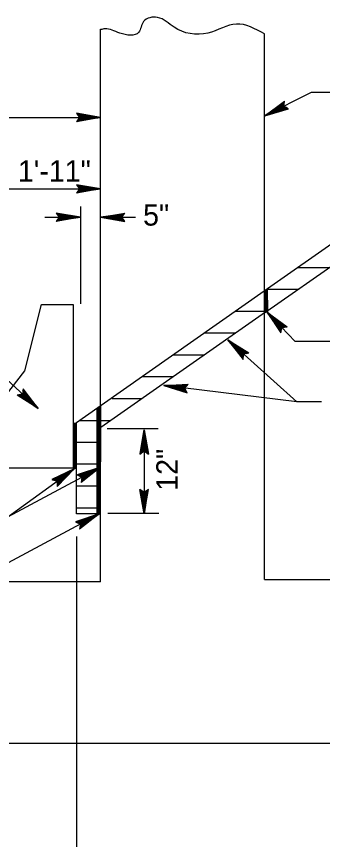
# Model space of a CAD drawing. Extents: x 1553195 to 1553792, y 810516 to 810787.
# Drawn here: x 1553765.27 to 1553772.77, y 810723.14 to 810743.32 of the extents above; entities that cross this region are included whole.
import ezdxf

# ---------------------------------------------------------------- set-up
doc = ezdxf.new("R2010")
doc.units = 0
doc.layers.add('Old_Level_28', color=7, linetype='Continuous')

msp = doc.modelspace()

# ---------------------------------------------------------------- linework, layer by layer
at = {"layer": 'Old_Level_28'}
for p, q in [((1553767.332, 810729.461), (1553767.332, 810743.008)), ((1553771.348, 810729.513), (1553771.348, 810742.899)), ((1553772.494, 810741.457), (1553771.357, 810740.888)), ((1553773.479, 810741.457), (1553772.494, 810741.457)), ((1553771.357, 810740.888), (1553771.843, 810741.248)), ((1553771.357, 810740.888), (1553771.839, 810741.23)), ((1553771.837, 810741.21), (1553771.357, 810740.888)), ((1553771.357, 810740.888), (1553771.835, 810741.193)), ((1553771.83, 810741.175), (1553771.357, 810740.888)), ((1553771.357, 810740.888), (1553771.826, 810741.155)), ((1553771.823, 810741.137), (1553771.357, 810740.888)), ((1553771.822, 810741.122), (1553771.357, 810740.888)), ((1553771.822, 810741.122), (1553771.843, 810741.248)), ((1553771.937, 810741.061), (1553771.822, 810741.122)), ((1553767.332, 810740.846), (1553766.739, 810740.948)), ((1553766.739, 810740.948), (1553766.815, 810740.846)), ((1553766.748, 810740.933), (1553767.332, 810740.846)), ((1553767.332, 810740.846), (1553766.759, 810740.92)), ((1553771.357, 810740.888), (1553771.837, 810741.11)), ((1553771.855, 810741.102), (1553771.357, 810740.888)), ((1553771.357, 810740.888), (1553771.871, 810741.095)), ((1553771.888, 810741.086), (1553771.357, 810740.888)), ((1553771.357, 810740.888), (1553771.904, 810741.077)), ((1553771.921, 810741.07), (1553771.357, 810740.888)), ((1553771.357, 810740.888), (1553771.937, 810741.061)), ((1553752.957, 810740.846), (1553767.332, 810740.846)), ((1553767.332, 810740.846), (1553766.739, 810740.739)), ((1553766.815, 810740.846), (1553766.739, 810740.739)), ((1553767.332, 810740.846), (1553766.748, 810740.754)), ((1553766.759, 810740.768), (1553767.332, 810740.846)), ((1553766.773, 810740.904), (1553767.332, 810740.846)), ((1553767.332, 810740.846), (1553766.773, 810740.784)), ((1553767.332, 810740.846), (1553766.781, 810740.888)), ((1553766.781, 810740.799), (1553767.332, 810740.846)), ((1553766.794, 810740.875), (1553767.332, 810740.846)), ((1553767.332, 810740.846), (1553766.794, 810740.813)), ((1553767.332, 810740.846), (1553766.806, 810740.859)), ((1553766.806, 810740.828), (1553767.332, 810740.846)), ((1553766.815, 810740.846), (1553767.332, 810740.846)), ((1553771.344, 810736.595), (1553776.608, 810740.281)), ((1553771.324, 810736.035), (1553776.864, 810739.914)), ((1553767.332, 810739.095), (1553766.739, 810739.197)), ((1553766.739, 810739.197), (1553766.815, 810739.095)), ((1553766.748, 810739.181), (1553767.332, 810739.095)), ((1553767.332, 810739.095), (1553766.759, 810739.168)), ((1553766.773, 810739.152), (1553767.332, 810739.095)), ((1553767.332, 810739.095), (1553766.781, 810739.137)), ((1553766.794, 810739.123), (1553767.332, 810739.095)), ((1553767.332, 810739.095), (1553766.806, 810739.108)), ((1553764.653, 810739.095), (1553767.332, 810739.095)), ((1553767.332, 810739.095), (1553766.739, 810738.988)), ((1553766.815, 810739.095), (1553766.739, 810738.988)), ((1553767.332, 810739.095), (1553766.748, 810739.004)), ((1553766.759, 810739.017), (1553767.332, 810739.095)), ((1553767.332, 810739.095), (1553766.773, 810739.032)), ((1553766.781, 810739.048), (1553767.332, 810739.095)), ((1553767.332, 810739.095), (1553766.794, 810739.061)), ((1553766.806, 810739.077), (1553767.332, 810739.095)), ((1553766.815, 810739.095), (1553767.332, 810739.095)), ((1553766.837, 810738.399), (1553766.243, 810738.501)), ((1553766.243, 810738.501), (1553766.319, 810738.399)), ((1553766.837, 810738.662), (1553766.837, 810736.277)), ((1553767.328, 810738.399), (1553767.924, 810738.501)), ((1553767.848, 810738.399), (1553767.924, 810738.501)), ((1553765.961, 810738.399), (1553766.837, 810738.399)), ((1553766.837, 810738.399), (1553766.243, 810738.292)), ((1553766.319, 810738.399), (1553766.243, 810738.292)), ((1553766.252, 810738.486), (1553766.837, 810738.399)), ((1553766.837, 810738.399), (1553766.252, 810738.308)), ((1553766.837, 810738.399), (1553766.263, 810738.473)), ((1553766.263, 810738.321), (1553766.837, 810738.399)), ((1553766.277, 810738.457), (1553766.837, 810738.399)), ((1553766.837, 810738.399), (1553766.277, 810738.337)), ((1553766.837, 810738.399), (1553766.286, 810738.441)), ((1553766.286, 810738.353), (1553766.837, 810738.399)), ((1553766.299, 810738.428), (1553766.837, 810738.399)), ((1553766.837, 810738.399), (1553766.299, 810738.366)), ((1553766.837, 810738.399), (1553766.311, 810738.412)), ((1553766.311, 810738.382), (1553766.837, 810738.399)), ((1553766.319, 810738.399), (1553766.837, 810738.399)), ((1553767.328, 810738.399), (1553767.91, 810738.486)), ((1553767.901, 810738.473), (1553767.328, 810738.399)), ((1553767.328, 810738.399), (1553767.891, 810738.457)), ((1553767.879, 810738.441), (1553767.328, 810738.399)), ((1553767.328, 810738.399), (1553767.868, 810738.428)), ((1553767.857, 810738.412), (1553767.328, 810738.399)), ((1553767.328, 810738.399), (1553768.19, 810738.399)), ((1553767.328, 810738.399), (1553767.924, 810738.292)), ((1553767.91, 810738.308), (1553767.328, 810738.399)), ((1553767.328, 810738.399), (1553767.901, 810738.321)), ((1553767.891, 810738.337), (1553767.328, 810738.399)), ((1553767.328, 810738.399), (1553767.879, 810738.353)), ((1553767.868, 810738.366), (1553767.328, 810738.399)), ((1553767.328, 810738.399), (1553767.857, 810738.382)), ((1553767.848, 810738.399), (1553767.328, 810738.399)), ((1553767.924, 810738.292), (1553767.848, 810738.399)), ((1553772.159, 810737.168), (1553772.948, 810737.168)), ((1553767.348, 810733.793), (1553771.346, 810736.592)), ((1553771.412, 810736.633), (1553772.197, 810736.633)), ((1553771.426, 810736.108), (1553771.426, 810736.65)), ((1553765.477, 810734.634), (1553765.879, 810736.259)), ((1553765.879, 810736.259), (1553766.661, 810736.259)), ((1553766.661, 810736.259), (1553766.661, 810732.243)), ((1553767.335, 810733.25), (1553771.373, 810736.077)), ((1553770.63, 810736.097), (1553771.441, 810736.097)), ((1553772.106, 810735.35), (1553771.417, 810736.074)), ((1553771.417, 810736.074), (1553771.904, 810735.715)), ((1553771.417, 810736.074), (1553771.751, 810735.568)), ((1553771.755, 810735.588), (1553771.417, 810736.074)), ((1553771.417, 810736.074), (1553771.759, 810735.606)), ((1553771.761, 810735.624), (1553771.417, 810736.074)), ((1553771.417, 810736.074), (1553771.764, 810735.644)), ((1553771.768, 810735.662), (1553771.417, 810736.074)), ((1553771.417, 810736.074), (1553771.77, 810735.682)), ((1553771.773, 810735.697), (1553771.417, 810736.074)), ((1553771.794, 810735.702), (1553771.417, 810736.074)), ((1553771.417, 810736.074), (1553771.813, 810735.702)), ((1553771.828, 810735.704), (1553771.417, 810736.074)), ((1553771.417, 810736.074), (1553771.85, 810735.708)), ((1553771.868, 810735.711), (1553771.417, 810736.074)), ((1553771.417, 810736.074), (1553771.884, 810735.712)), ((1553763.619, 810735.72), (1553765.799, 810733.706)), ((1553771.751, 810735.568), (1553771.773, 810735.697)), ((1553771.773, 810735.697), (1553771.904, 810735.715)), ((1553769.864, 810735.564), (1553770.644, 810735.564)), ((1553772.143, 810733.872), (1553770.455, 810735.392)), ((1553770.455, 810735.392), (1553770.97, 810735.073)), ((1553770.455, 810735.392), (1553770.828, 810734.914)), ((1553770.828, 810734.934), (1553770.455, 810735.392)), ((1553770.455, 810735.392), (1553770.83, 810734.952)), ((1553770.835, 810734.97), (1553770.455, 810735.392)), ((1553770.455, 810735.392), (1553770.835, 810734.99)), ((1553770.837, 810735.008), (1553770.455, 810735.392)), ((1553770.455, 810735.392), (1553770.839, 810735.028)), ((1553770.839, 810735.046), (1553770.455, 810735.392)), ((1553770.857, 810735.05), (1553770.455, 810735.392)), ((1553770.455, 810735.392), (1553770.877, 810735.054)), ((1553770.895, 810735.057), (1553770.455, 810735.392)), ((1553770.455, 810735.392), (1553770.914, 810735.061)), ((1553770.933, 810735.064), (1553770.455, 810735.392)), ((1553770.455, 810735.392), (1553770.95, 810735.07)), ((1553773.09, 810735.35), (1553772.106, 810735.35)), ((1553770.839, 810735.046), (1553770.97, 810735.073)), ((1553769.11, 810735.028), (1553769.888, 810735.028)), ((1553770.828, 810734.914), (1553770.839, 810735.046)), ((1553764.653, 810733.581), (1553765.477, 810734.634)), ((1553768.344, 810734.49), (1553769.106, 810734.49)), ((1553768.879, 810734.272), (1553769.481, 810734.304)), ((1553768.879, 810734.272), (1553769.468, 810734.291)), ((1553769.457, 810734.277), (1553768.879, 810734.272)), ((1553772.143, 810733.872), (1553768.879, 810734.272)), ((1553768.879, 810734.272), (1553769.457, 810734.095)), ((1553769.448, 810734.112), (1553768.879, 810734.272)), ((1553768.879, 810734.272), (1553769.439, 810734.128)), ((1553769.428, 810734.144), (1553768.879, 810734.272)), ((1553768.879, 810734.272), (1553769.422, 810734.161)), ((1553769.412, 810734.177), (1553768.879, 810734.272)), ((1553768.879, 810734.272), (1553769.402, 810734.193)), ((1553769.395, 810734.208), (1553768.879, 810734.272)), ((1553769.403, 810734.223), (1553768.879, 810734.272)), ((1553768.879, 810734.272), (1553769.417, 810734.237)), ((1553769.435, 810734.25), (1553768.879, 810734.272)), ((1553768.879, 810734.272), (1553769.444, 810734.263)), ((1553769.395, 810734.208), (1553769.481, 810734.304)), ((1553765.415, 810734.058), (1553765.288, 810734.035)), ((1553765.43, 810734.189), (1553765.415, 810734.058)), ((1553765.415, 810734.058), (1553765.799, 810733.706)), ((1553765.419, 810734.095), (1553765.799, 810733.706)), ((1553765.799, 810733.706), (1553765.419, 810734.078)), ((1553765.799, 810733.706), (1553765.421, 810734.116)), ((1553765.425, 810734.133), (1553765.799, 810733.706)), ((1553765.428, 810734.171), (1553765.799, 810733.706)), ((1553765.799, 810733.706), (1553765.428, 810734.151)), ((1553765.799, 810733.706), (1553765.43, 810734.189)), ((1553769.457, 810734.095), (1553769.395, 810734.208)), ((1553765.799, 810733.706), (1553765.288, 810734.035)), ((1553765.799, 810733.706), (1553765.308, 810734.038)), ((1553765.325, 810734.039), (1553765.799, 810733.706)), ((1553765.799, 810733.706), (1553765.341, 810734.045)), ((1553765.361, 810734.049), (1553765.799, 810733.706)), ((1553765.799, 810733.706), (1553765.379, 810734.051)), ((1553765.399, 810734.053), (1553765.799, 810733.706)), ((1553767.611, 810733.955), (1553768.344, 810733.955)), ((1553772.749, 810733.872), (1553772.143, 810733.872)), ((1553766.661, 810733.312), (1553767.344, 810733.788)), ((1553767.25, 810731.11), (1553767.25, 810733.721)), ((1553767.266, 810731.122), (1553767.266, 810733.731)), ((1553767.282, 810731.135), (1553767.282, 810733.744)), ((1553767.308, 810733.754), (1553767.283, 810733.606)), ((1553767.283, 810733.606), (1553767.283, 810733.739)), ((1553767.29, 810732.284), (1553767.29, 810733.75)), ((1553767.295, 810732.284), (1553767.295, 810733.75)), ((1553767.301, 810732.284), (1553767.301, 810733.75)), ((1553767.304, 810732.291), (1553767.304, 810733.757)), ((1553767.308, 810732.297), (1553767.308, 810733.761)), ((1553767.311, 810733.481), (1553767.308, 810733.754)), ((1553767.332, 810733.774), (1553767.311, 810733.481)), ((1553767.315, 810732.297), (1553767.315, 810733.764)), ((1553767.319, 810732.308), (1553767.319, 810733.77)), ((1553767.324, 810732.311), (1553767.324, 810733.774)), ((1553767.331, 810733.419), (1553767.324, 810733.761)), ((1553767.324, 810733.761), (1553767.328, 810733.523)), ((1553767.328, 810733.523), (1553767.328, 810733.761)), ((1553767.328, 810733.761), (1553767.331, 810733.543)), ((1553767.331, 810733.543), (1553767.332, 810733.774)), ((1553766.67, 810732.237), (1553766.67, 810733.361)), ((1553766.679, 810732.233), (1553766.679, 810733.354)), ((1553766.688, 810732.235), (1553766.688, 810733.357)), ((1553766.688, 810732.815), (1553766.688, 810733.344)), ((1553766.692, 810732.235), (1553766.692, 810733.357)), ((1553766.695, 810732.237), (1553766.695, 810733.361)), ((1553766.702, 810732.235), (1553766.702, 810733.357)), ((1553766.706, 810732.81), (1553766.706, 810733.344)), ((1553766.71, 810732.235), (1553766.71, 810733.357)), ((1553766.71, 810732.815), (1553766.71, 810733.344)), ((1553766.715, 810732.817), (1553766.715, 810733.348)), ((1553766.717, 810732.237), (1553766.717, 810733.361)), ((1553766.717, 810732.819), (1553766.717, 810733.353)), ((1553766.719, 810732.233), (1553766.719, 810733.354)), ((1553766.719, 810732.819), (1553766.719, 810733.353)), ((1553766.721, 810732.822), (1553766.721, 810733.354)), ((1553766.724, 810732.235), (1553766.724, 810733.357)), ((1553766.728, 810732.828), (1553766.728, 810733.357)), ((1553766.731, 810732.235), (1553766.731, 810733.357)), ((1553766.732, 810732.83), (1553766.732, 810733.361)), ((1553766.732, 810732.828), (1553766.732, 810733.361)), ((1553766.732, 810732.237), (1553766.732, 810733.361)), ((1553766.737, 810732.242), (1553766.737, 810733.363)), ((1553766.737, 810731.128), (1553766.737, 810733.363)), ((1553766.817, 810733.419), (1553767.568, 810733.419)), ((1553767.268, 810733.204), (1553767.308, 810733.233)), ((1553768.741, 810733.208), (1553767.49, 810733.208)), ((1553768.397, 810733.188), (1553768.292, 810732.592)), ((1553768.305, 810732.604), (1553768.397, 810733.188)), ((1553768.397, 810733.188), (1553768.321, 810732.614)), ((1553768.337, 810732.624), (1553768.397, 810733.188)), ((1553768.397, 810733.188), (1553768.35, 810732.634)), ((1553768.368, 810732.648), (1553768.397, 810733.188)), ((1553768.397, 810733.188), (1553768.383, 810732.657)), ((1553768.397, 810733.188), (1553768.397, 810731.13)), ((1553768.397, 810733.188), (1553768.504, 810732.592)), ((1553768.397, 810732.67), (1553768.397, 810733.188)), ((1553768.412, 810732.657), (1553768.397, 810733.188)), ((1553768.397, 810733.188), (1553768.428, 810732.648)), ((1553768.441, 810732.634), (1553768.397, 810733.188)), ((1553768.397, 810733.188), (1553768.457, 810732.624)), ((1553768.475, 810732.614), (1553768.397, 810733.188)), ((1553768.397, 810733.188), (1553768.488, 810732.604)), ((1553766.715, 810732.885), (1553767.335, 810732.885)), ((1553768.292, 810732.592), (1553768.397, 810732.67)), ((1553768.397, 810732.67), (1553768.504, 810732.592)), ((1553766.661, 810732.243), (1553764.653, 810732.243)), ((1553765.059, 810731.054), (1553767.332, 810732.27)), ((1553766.737, 810732.35), (1553767.335, 810732.35)), ((1553767.332, 810732.27), (1553766.757, 810732.081)), ((1553766.773, 810732.073), (1553767.332, 810732.27)), ((1553767.332, 810732.27), (1553766.793, 810732.064)), ((1553766.808, 810732.058), (1553767.332, 810732.27)), ((1553767.332, 810732.27), (1553766.823, 810732.048)), ((1553766.842, 810732.042), (1553767.332, 810732.27)), ((1553767.332, 810732.27), (1553766.855, 810731.895)), ((1553767.332, 810732.27), (1553766.859, 810732.033)), ((1553767.332, 810732.27), (1553766.859, 810731.915)), ((1553766.862, 810731.935), (1553767.332, 810732.27)), ((1553767.332, 810732.27), (1553766.864, 810731.953)), ((1553766.866, 810731.971), (1553767.332, 810732.27)), ((1553767.332, 810732.27), (1553766.868, 810731.989)), ((1553766.872, 810732.006), (1553767.332, 810732.27)), ((1553766.875, 810732.024), (1553767.332, 810732.27)), ((1553767.283, 810731.141), (1553767.282, 810732.277)), ((1553767.295, 810731.137), (1553767.295, 810732.275)), ((1553765.059, 810731.054), (1553766.679, 810732.23)), ((1553766.679, 810732.23), (1553766.135, 810731.966)), ((1553766.155, 810731.962), (1553766.679, 810732.23)), ((1553766.679, 810732.23), (1553766.172, 810731.955)), ((1553766.188, 810731.95), (1553766.679, 810732.23)), ((1553766.679, 810732.23), (1553766.208, 810731.941)), ((1553766.226, 810731.937), (1553766.679, 810732.23)), ((1553766.679, 810732.23), (1553766.241, 810731.93)), ((1553766.679, 810732.23), (1553766.262, 810731.795)), ((1553766.262, 810731.926), (1553766.679, 810732.23)), ((1553766.262, 810731.908), (1553766.679, 810732.23)), ((1553766.679, 810732.23), (1553766.262, 810731.888)), ((1553766.262, 810731.871), (1553766.679, 810732.23)), ((1553766.679, 810732.23), (1553766.262, 810731.85)), ((1553766.262, 810731.832), (1553766.679, 810732.23)), ((1553766.679, 810732.23), (1553766.262, 810731.815)), ((1553766.757, 810732.081), (1553766.875, 810732.024)), ((1553766.135, 810731.966), (1553766.262, 810731.926)), ((1553766.262, 810731.926), (1553766.262, 810731.795)), ((1553766.875, 810732.024), (1553766.855, 810731.895)), ((1553766.732, 810731.815), (1553767.335, 810731.815)), ((1553768.397, 810731.13), (1553768.292, 810731.725)), ((1553768.397, 810731.65), (1553768.292, 810731.725)), ((1553768.397, 810731.13), (1553768.305, 810731.715)), ((1553768.321, 810731.704), (1553768.397, 810731.13)), ((1553768.397, 810731.13), (1553768.337, 810731.695)), ((1553768.35, 810731.683), (1553768.397, 810731.13)), ((1553768.397, 810731.13), (1553768.368, 810731.672)), ((1553768.383, 810731.662), (1553768.397, 810731.13)), ((1553768.397, 810731.13), (1553768.504, 810731.725)), ((1553768.504, 810731.725), (1553768.397, 810731.65)), ((1553768.488, 810731.715), (1553768.397, 810731.13)), ((1553768.397, 810731.13), (1553768.475, 810731.704)), ((1553768.457, 810731.695), (1553768.397, 810731.13)), ((1553768.397, 810731.13), (1553768.441, 810731.683)), ((1553768.428, 810731.672), (1553768.397, 810731.13)), ((1553768.397, 810731.13), (1553768.412, 810731.662)), ((1553768.397, 810731.65), (1553768.397, 810731.13)), ((1553766.741, 810731.277), (1553767.324, 810731.277)), ((1553764.837, 810729.808), (1553767.295, 810731.123)), ((1553767.295, 810731.123), (1553766.719, 810730.934)), ((1553766.735, 810730.926), (1553767.295, 810731.123)), ((1553766.744, 810731.135), (1553767.331, 810731.135)), ((1553767.295, 810731.123), (1553766.755, 810730.917)), ((1553766.77, 810730.91), (1553767.295, 810731.123)), ((1553767.295, 810731.123), (1553766.786, 810730.901)), ((1553766.804, 810730.894), (1553767.295, 810731.123)), ((1553767.295, 810731.123), (1553766.817, 810730.748)), ((1553767.295, 810731.123), (1553766.822, 810730.885)), ((1553767.295, 810731.123), (1553766.822, 810730.768)), ((1553766.823, 810730.788), (1553767.295, 810731.123)), ((1553767.295, 810731.123), (1553766.826, 810730.806)), ((1553766.828, 810730.823), (1553767.295, 810731.123)), ((1553767.295, 810731.123), (1553766.83, 810730.842)), ((1553766.835, 810730.859), (1553767.295, 810731.123)), ((1553766.837, 810730.877), (1553767.295, 810731.123)), ((1553768.757, 810731.137), (1553767.506, 810731.137)), ((1553766.719, 810730.934), (1553766.837, 810730.877)), ((1553766.837, 810730.877), (1553766.817, 810730.748)), ((1553766.737, 810730.571), (1553766.737, 810707.494)), ((1553767.332, 810729.461), (1553764.435, 810729.461)), ((1553771.348, 810729.513), (1553771.348, 810729.513)), ((1553771.348, 810729.513), (1553774.248, 810729.513)), ((1553774.248, 810725.497), (1553764.422, 810725.497))]:
    msp.add_line(p, q, dxfattribs=at)
for points in [[(1553771.348, 810736.595), (1553771.35, 810736.057), (1553771.35, 810736.595), (1553771.357, 810736.059), (1553771.357, 810736.604), (1553771.364, 810736.064), (1553771.359, 810736.606), (1553771.37, 810736.068), (1553771.359, 810736.248), (1553771.359, 810736.061), (1553771.35, 810736.25), (1553771.357, 810736.057), (1553771.354, 810736.112), (1553771.357, 810736.059), (1553771.35, 810736.083), (1553771.364, 810736.07), (1553771.373, 810736.07), (1553771.364, 810736.606), (1553771.377, 810736.074), (1553771.364, 810736.608), (1553771.373, 810736.074), (1553771.37, 810736.61), (1553771.383, 810736.081), (1553771.374, 810736.614), (1553771.386, 810736.081), (1553771.377, 810736.619), (1553771.386, 810736.083), (1553771.383, 810736.619), (1553771.39, 810736.086), (1553771.386, 810736.619), (1553771.395, 810736.086), (1553771.39, 810736.628)], [(1553771.39, 810736.628), (1553771.397, 810736.088), (1553771.397, 810736.633), (1553771.402, 810736.09), (1553771.399, 810736.633), (1553771.408, 810736.095), (1553771.403, 810736.634), (1553771.412, 810736.097), (1553771.408, 810736.637), (1553771.417, 810736.102), (1553771.41, 810736.641), (1553771.417, 810736.108), (1553771.412, 810736.644), (1553771.423, 810736.103), (1553771.417, 810736.646), (1553771.426, 810736.108), (1553771.423, 810736.646)], [(1553767.295, 810733.206), (1553767.297, 810733.221), (1553767.297, 810731.13), (1553767.297, 810733.201), (1553767.311, 810731.144), (1553767.315, 810733.206), (1553767.324, 810731.144), (1553767.311, 810733.223), (1553767.308, 810731.135), (1553767.304, 810733.217), (1553767.324, 810731.135), (1553767.317, 810733.255), (1553767.301, 810731.128), (1553767.319, 810732.408), (1553767.321, 810731.659), (1553767.324, 810732.217), (1553767.324, 810731.648), (1553767.311, 810731.135), (1553767.332, 810733.659), (1553767.319, 810731.135)], [(1553767.331, 810733.424), (1553767.324, 810733.764), (1553767.328, 810733.424)], [(1553766.666, 810732.242), (1553766.663, 810732.779), (1553766.666, 810733.315)], [(1553766.683, 810732.243), (1553766.677, 810732.788), (1553766.675, 810733.317)], [(1553766.703, 810732.243), (1553766.69, 810732.797), (1553766.679, 810733.326)], [(1553766.708, 810732.242), (1553766.695, 810732.803), (1553766.688, 810733.33)], [(1553766.708, 810732.243), (1553766.702, 810732.806), (1553766.695, 810733.334)], [(1553766.697, 810733.337), (1553766.706, 810732.808), (1553766.703, 810733.339)]]:
    msp.add_lwpolyline(points, dxfattribs=at)
msp.add_spline([(1553771.348, 810742.895), (1553770.664, 810743.137), (1553769.959, 810742.914), (1553769.132, 810743.057), (1553768.728, 810743.299), (1553768.386, 810743.197), (1553768.266, 810742.934), (1553767.801, 810742.914), (1553767.439, 810743.017), (1553767.331, 810743.001)], degree=3, dxfattribs=at)

# ---------------------------------------------------------------- texts
for s, p in [('1\'-11"', (1553765.303, 810739.272)), ('5" ', (1553768.373, 810738.194))]:
    msp.add_text(s, height=0.5249, dxfattribs=at).set_placement(p)
msp.add_text('12"', height=0.5249, rotation=90, dxfattribs=at).set_placement((1553769.222, 810731.691))

doc.saveas('drawing.dxf')
